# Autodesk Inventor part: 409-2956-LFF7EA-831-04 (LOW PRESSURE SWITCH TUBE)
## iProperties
Created: 2011-01
Material: 3/8" OD TUBE - SS
Document SubType Name: Modeling
Designer: S. Boerckel
Engineer: Steve Boerckel
Mass: 199.016 g
Surface Area: 326.016 cm^2
Volume: 24.784 cm^3
Density: 8.03 g/cm^3
User Status: CUT/BEND
Description: PRESSURE SWITCH LOW TUBE
LGTH: 25.472 in
Author: S. Boerckel
Revision Number: 0
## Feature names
1. Sweep1
